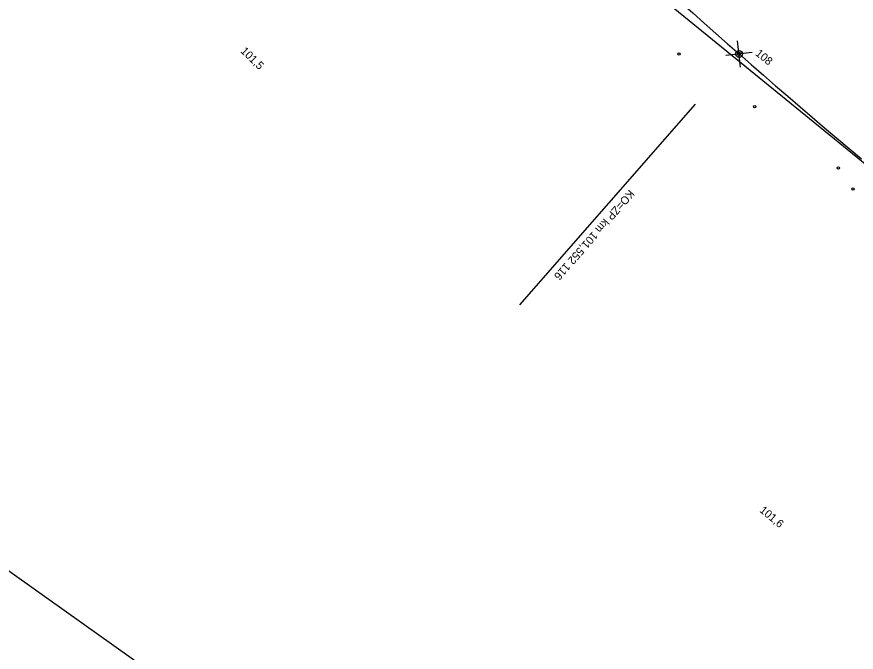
# Model space of a CAD drawing. Extents: x -505028 to -503155, y -1080361 to -1077947.
# Drawn here: x -504080.9 to -503955.1, y -1079473.5 to -1079378.2 of the extents above; entities that cross this region are included whole.
import ezdxf

# ---------------------------------------------------------------- set-up
doc = ezdxf.new("R2010")
doc.units = 0
for name, color, linetype in [('C3D-BOD', 7, 'Continuous'), ('C3D-TRASA-POPIS', 7, 'Continuous'), ('C3D_Povrch - Popis', 7, 'Continuous'), ('C3D_Trasa-Popisy trasy', 7, 'Continuous'), ('Default', 7, 'Continuous'), ('Trasa-Geometrie', 7, 'Continuous'), ('Vrstva 24', 7, 'Continuous'), ('Vrstva 63', 7, 'Continuous'), ('ŽKN stavba druh', 7, 'Continuous')]:
    doc.layers.add(name, color=color, linetype=linetype)

# ---------------------------------------------------------------- blocks, each defined once
blk = doc.blocks.new('C045')
at = {"layer": 'ŽKN stavba druh'}
blk.add_circle((0, 0), 1.75, dxfattribs=at)
blk = doc.blocks.new('AeccTickCircle')
at = {"layer": 'Default'}
blk.add_circle((0, 0), 5, dxfattribs=at)
blk = doc.blocks.new('_U969')
at = {"layer": 'Default'}
for p, q in [((-7.07, -7.07), (7.07, 7.07)), ((-7.07, 7.07), (7.07, -7.07))]:
    blk.add_line(p, q, dxfattribs=at)

msp = doc.modelspace()

# ---------------------------------------------------------------- linework, layer by layer
at = {"layer": 'C3D-TRASA-POPIS'}
msp.add_line((-503979.21, -1079391.28), (-504005.56, -1079421.38), dxfattribs=at)
at = {"layer": 'Default'}
msp.add_line((-503874.08, -1079465.25), (-504024.59, -1079342.51), dxfattribs=at)
msp.add_circle((-503972.63, -1079383.76), 0.25, dxfattribs=at)
at = {"layer": 'Trasa-Geometrie'}
msp.add_lwpolyline([(-503972.63, -1079383.76), (-503970.8, -1079385.35), (-503968.98, -1079386.94), (-503967.15, -1079388.52), (-503965.32, -1079390.1), (-503963.48, -1079391.68), (-503961.64, -1079393.25), (-503959.8, -1079394.82), (-503957.96, -1079396.39), (-503956.11, -1079397.95), (-503954.26, -1079399.51)], dxfattribs=at)
msp.add_arc((-503267.77, -1078578.72), 1070, 220.84897, 228.79592, dxfattribs=at)
at = {"layer": 'Vrstva 63'}
msp.add_lwpolyline([(-503746.76, -1079335.57), (-503919, -1079577.52), (-504261.16, -1079333.94), (-504088.92, -1079091.99)], close=True, dxfattribs=at)

# ---------------------------------------------------------------- block references
at = {"layer": 'C3D-BOD', "xscale": 0.19999999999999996, "yscale": 0.1999999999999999, "rotation": 141.804}
msp.add_blockref('_U969', (-503972.63, -1079383.76), dxfattribs=at)
at = {"layer": 'C3D-TRASA-POPIS', "xscale": 0.09999999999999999, "yscale": 0.1, "rotation": -41.20408476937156}
msp.add_blockref('AeccTickCircle', (-503972.63, -1079383.76), dxfattribs=at)
at = {"layer": 'Vrstva 24', "xscale": 0.1, "yscale": 0.10000000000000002}
for p in [(-503981.62, -1079383.79), (-503981.62, -1079383.79), (-503970.27, -1079391.66), (-503970.27, -1079391.66), (-503970.27, -1079391.66), (-503970.27, -1079391.66), (-503957.72, -1079400.87), (-503957.72, -1079400.87), (-503957.72, -1079400.87), (-503957.72, -1079400.87), (-503955.52, -1079404.01), (-503955.52, -1079404.01)]:
    msp.add_blockref('C045', p, dxfattribs=at)

# ---------------------------------------------------------------- texts
at = {"layer": 'C3D-TRASA-POPIS'}
msp.add_text('KO=ZP km 101,552 116', height=1.2, rotation=228.7959, dxfattribs=at).set_placement((-503989.09, -1079404.04))
at = {"layer": 'C3D_Povrch - Popis'}
msp.add_text('108', height=1.2, rotation=320.804, dxfattribs=at).set_placement((-503970.28, -1079383.85))
at = {"layer": 'C3D_Trasa-Popisy trasy'}
for s, rotation, p in [('101,5', 316.0052, (-504047.47, -1079383.43)), ('101,6', 320.5415, (-503969.65, -1079452.39))]:
    msp.add_text(s, height=1.2, rotation=rotation, dxfattribs=at).set_placement(p)

doc.saveas('drawing.dxf')
